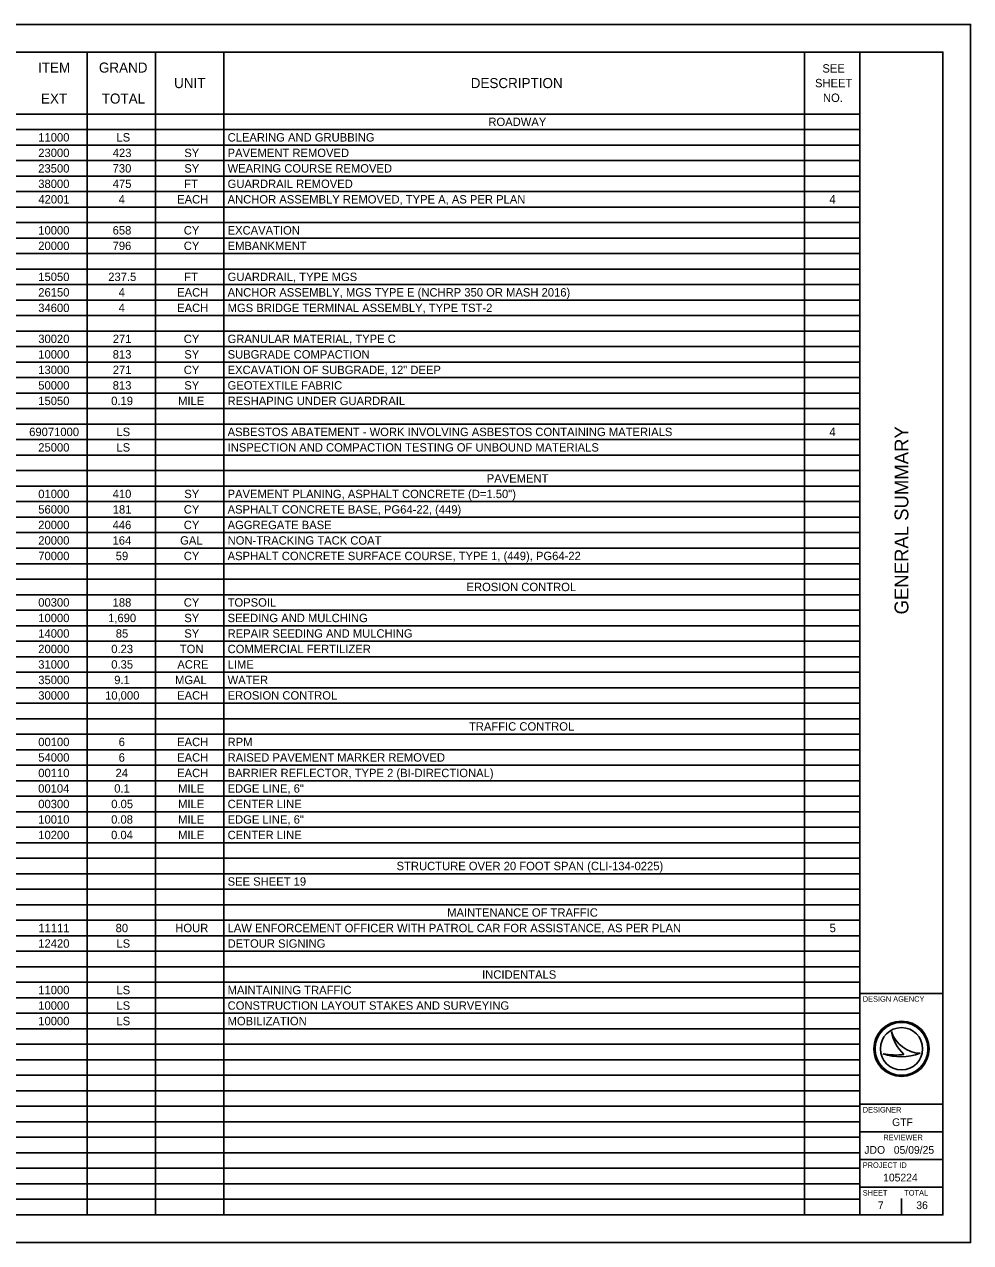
# Model space of a CAD drawing. Extents: x -98 to 34, y 0 to 58.
# Drawn here: x 16.9 to 34, y 0 to 22 of the extents above; entities that cross this region are included whole.
import ezdxf

# ---------------------------------------------------------------- set-up
doc = ezdxf.new("R2010")
doc.units = 0
for name, color, linetype in [('Default', 7, 'Continuous'), ('SH_Border', 7, 'Continuous'), ('SH_Cut_Line', 7, 'Continuous'), ('SH_Data', 7, 'Continuous')]:
    doc.layers.add(name, color=color, linetype=linetype)

msp = doc.modelspace()

# ---------------------------------------------------------------- linework, layer by layer
at = {"layer": 'Default'}
for p, q in [((1.5, 21.5), (32, 21.5)), ((18.035, 21.5), (18.035, 0.502)), ((19.27, 21.5), (19.27, 0.502)), ((20.505, 21.5), (20.505, 0.502)), ((30.995, 21.5), (30.995, 0.502)), ((32, 21.5), (32, 0.502)), ((1.5, 20.38), (32, 20.38)), ((1.5, 20.1), (32, 20.1)), ((1.5, 19.82), (32, 19.82)), ((1.5, 19.54), (32, 19.54)), ((1.5, 19.26), (32, 19.26)), ((1.5, 18.98), (32, 18.98)), ((1.5, 18.7), (32, 18.7)), ((1.5, 18.42), (32, 18.42)), ((1.5, 18.14), (32, 18.14)), ((1.5, 17.86), (32, 17.86)), ((1.5, 17.58), (32, 17.58)), ((1.5, 17.3), (32, 17.3)), ((1.5, 17.021), (32, 17.021)), ((1.5, 16.741), (32, 16.741)), ((1.5, 16.461), (32, 16.461)), ((1.5, 16.181), (32, 16.181)), ((1.5, 15.901), (32, 15.901)), ((1.5, 15.621), (32, 15.621)), ((1.5, 15.341), (32, 15.341)), ((1.5, 15.061), (32, 15.061)), ((1.5, 14.781), (32, 14.781)), ((1.5, 14.501), (32, 14.501)), ((1.5, 14.221), (32, 14.221)), ((1.5, 13.941), (32, 13.941)), ((1.5, 13.661), (32, 13.661)), ((1.5, 13.381), (32, 13.381)), ((1.5, 13.101), (32, 13.101)), ((1.5, 12.821), (32, 12.821)), ((1.5, 12.541), (32, 12.541)), ((1.5, 12.261), (32, 12.261)), ((1.5, 11.981), (32, 11.981)), ((1.5, 11.701), (32, 11.701)), ((1.5, 11.421), (32, 11.421)), ((1.5, 11.141), (32, 11.141)), ((1.5, 10.861), (32, 10.861)), ((1.5, 10.581), (32, 10.581)), ((1.5, 10.301), (32, 10.301)), ((1.5, 10.021), (32, 10.021)), ((1.5, 9.741), (32, 9.741)), ((1.5, 9.461), (32, 9.461)), ((1.5, 9.181), (32, 9.181)), ((1.5, 8.901), (32, 8.901)), ((1.5, 8.621), (32, 8.621)), ((1.5, 8.342), (32, 8.342)), ((1.5, 8.062), (32, 8.062)), ((1.5, 7.782), (32, 7.782)), ((1.5, 7.502), (32, 7.502)), ((1.5, 7.222), (32, 7.222)), ((1.5, 6.942), (32, 6.942)), ((1.5, 6.662), (32, 6.662)), ((1.5, 6.382), (32, 6.382)), ((1.5, 6.102), (32, 6.102)), ((1.5, 5.822), (32, 5.822)), ((1.5, 5.542), (32, 5.542)), ((1.5, 5.262), (32, 5.262)), ((1.5, 4.982), (32, 4.982)), ((1.5, 4.702), (32, 4.702)), ((1.5, 4.422), (32, 4.422)), ((1.5, 4.142), (32, 4.142)), ((1.5, 3.862), (32, 3.862)), ((1.5, 3.582), (32, 3.582)), ((1.5, 3.302), (32, 3.302)), ((1.5, 3.022), (32, 3.022)), ((1.5, 2.742), (32, 2.742)), ((1.5, 2.462), (32, 2.462)), ((1.5, 2.182), (32, 2.182)), ((1.5, 1.902), (32, 1.902)), ((1.5, 1.622), (32, 1.622)), ((1.5, 1.342), (32, 1.342)), ((1.5, 1.062), (32, 1.062)), ((1.5, 0.782), (32, 0.782)), ((1.5, 0.502), (32, 0.502))]:
    msp.add_line(p, q, dxfattribs=at)
at = {"layer": 'SH_Border'}
for p, q in [((32, 0.5), (32, 21.5)), ((32, 4.5), (33.5, 4.5)), ((32, 2.5), (33.5, 2.5)), ((32, 2), (33.5, 2)), ((32, 1.5), (33.5, 1.5)), ((32, 1), (33.5, 1))]:
    msp.add_line(p, q, dxfattribs=at)
msp.add_lwpolyline([(1.5, 21.5), (33.5, 21.5), (33.5, 0.5), (1.5, 0.5)], close=True, dxfattribs=at)
at = {"layer": 'SH_Cut_Line'}
msp.add_lwpolyline([(0, 0), (34, 0), (34, 22), (0, 22)], close=True, dxfattribs=at)
at = {"layer": 'SH_Data'}
for p, q in [((32.567, 3.81), (32.567, 3.81)), ((32.417, 3.41), (32.417, 3.41)), ((32.75, 3.5), (32.75, 3.5)), ((33.087, 3.419), (33.087, 3.419)), ((32.375, 0.675), (32.375, 0.675)), ((32.75, 0.5), (32.75, 0.8))]:
    msp.add_line(p, q, dxfattribs=at)
for radius in [0.5, 0.477, 0.477, 0.382]:
    msp.add_circle((32.75, 3.5), radius, dxfattribs=at)
for centre, radius, start, end in [((33.116, 3.998), 0.58, 198.9257, 198.9319), ((33.347, 3.97), 0.796, 191.6379, 191.6421), ((33.116, 3.998), 0.58, 198.9319, 267.1657), ((33.347, 3.97), 0.796, 191.6421, 226.0947), ((32.739, 4.37), 1.013, 251.4576, 290.0832), ((32.648, 4.654), 1.266, 259.4964, 259.4995), ((32.739, 4.37), 1.013, 251.4527, 251.4576), ((32.648, 4.654), 1.266, 259.4995, 276.6672)]:
    msp.add_arc(centre, radius, start, end, dxfattribs=at)

# ---------------------------------------------------------------- texts
at = {"layer": 'Default'}
for s, height, p in [('ITEM', 0.1818, (17.145, 21.129)), ('GRAND', 0.1818, (18.245, 21.129)), ('SEE ', 0.1515, (31.32, 21.129)), ('UNIT', 0.1818, (19.604, 20.849)), ('DESCRIPTION', 0.18181, (24.965, 20.849)), ('SHEET ', 0.1515, (31.187, 20.864)), ('EXT', 0.1818, (17.199, 20.569)), ('TOTAL', 0.1818, (18.297, 20.569)), ('NO.', 0.1515, (31.331, 20.599)), ('ROADWAY', 0.1515, (25.284, 20.164)), ('11000', 0.1515, (17.149, 19.884)), ('LS', 0.1515, (18.562, 19.884)), ('CLEARING AND GRUBBING', 0.15151, (20.571, 19.884)), ('23000', 0.1515, (17.149, 19.604)), ('423', 0.1515, (18.495, 19.604)), ('SY', 0.1515, (19.788, 19.604)), ('PAVEMENT REMOVED', 0.15151, (20.571, 19.604)), ('23500', 0.1515, (17.149, 19.324)), ('730', 0.1515, (18.493, 19.324)), ('SY', 0.1515, (19.788, 19.324)), ('WEARING COURSE REMOVED', 0.15151, (20.571, 19.324)), ('38000', 0.1515, (17.149, 19.045)), ('475', 0.1515, (18.495, 19.045)), ('FT', 0.1515, (19.786, 19.045)), ('GUARDRAIL REMOVED', 0.15151, (20.571, 19.045)), ('42001', 0.1515, (17.151, 18.765)), ('4', 0.152, (18.601, 18.765)), ('EACH', 0.1515, (19.659, 18.765)), ('ANCHOR ASSEMBLY REMOVED, TYPE A, AS PER PLAN', 0.15151, (20.571, 18.765)), ('4', 0.152, (31.446, 18.765)), ('10000', 0.1515, (17.149, 18.205)), ('658', 0.1515, (18.493, 18.205)), ('CY', 0.1515, (19.779, 18.205)), ('EXCAVATION', 0.1515, (20.571, 18.205)), ('20000', 0.1515, (17.149, 17.925)), ('796', 0.1515, (18.493, 17.925)), ('CY', 0.1515, (19.779, 17.925)), ('EMBANKMENT', 0.1515, (20.571, 17.925)), ('15050', 0.1515, (17.149, 17.365)), ('237.5', 0.1515, (18.414, 17.365)), ('FT', 0.1515, (19.786, 17.365)), ('GUARDRAIL, TYPE MGS', 0.15151, (20.571, 17.365)), ('26150', 0.1515, (17.149, 17.085)), ('4', 0.152, (18.601, 17.085)), ('EACH', 0.1515, (19.659, 17.085)), ('ANCHOR ASSEMBLY, MGS TYPE E (NCHRP 350 OR MASH 2016)', 0.15151, (20.571, 17.085)), ('34600', 0.1515, (17.149, 16.805)), ('4', 0.152, (18.601, 16.805)), ('EACH', 0.1515, (19.659, 16.805)), ('MGS BRIDGE TERMINAL ASSEMBLY, TYPE TST-2', 0.15151, (20.571, 16.805)), ('30020', 0.1515, (17.149, 16.245)), ('271', 0.1515, (18.495, 16.245)), ('CY', 0.1515, (19.779, 16.245)), ('GRANULAR MATERIAL, TYPE C', 0.15151, (20.571, 16.245)), ('10000', 0.1515, (17.149, 15.965)), ('813', 0.1515, (18.495, 15.965)), ('SY', 0.1515, (19.788, 15.965)), ('SUBGRADE COMPACTION', 0.15151, (20.571, 15.965)), ('13000', 0.1515, (17.149, 15.685)), ('271', 0.1515, (18.495, 15.685)), ('CY', 0.1515, (19.779, 15.685)), ('EXCAVATION OF SUBGRADE, 12" DEEP', 0.15151, (20.571, 15.685)), ('50000', 0.1515, (17.149, 15.405)), ('813', 0.1515, (18.495, 15.405)), ('SY', 0.1515, (19.788, 15.405)), ('GEOTEXTILE FABRIC', 0.15151, (20.571, 15.405)), ('15050', 0.1515, (17.149, 15.125)), ('0.19', 0.1515, (18.467, 15.125)), ('MILE', 0.1515, (19.676, 15.125)), ('RESHAPING UNDER GUARDRAIL', 0.15151, (20.571, 15.125)), ('69071000', 0.1515, (16.985, 14.565)), ('LS', 0.1515, (18.562, 14.565)), ('ASBESTOS ABATEMENT - WORK INVOLVING ASBESTOS CONTAINING MATERIALS', 0.15151, (20.571, 14.565)), ('4', 0.152, (31.446, 14.565)), ('25000', 0.1515, (17.149, 14.285)), ('LS', 0.1515, (18.562, 14.285)), ('INSPECTION AND COMPACTION TESTING OF UNBOUND MATERIALS', 0.15151, (20.571, 14.285)), ('PAVEMENT', 0.1515, (25.255, 13.725)), ('01000', 0.1515, (17.149, 13.445)), ('410', 0.1515, (18.493, 13.445)), ('SY', 0.1515, (19.788, 13.445)), ('PAVEMENT PLANING, ASPHALT CONCRETE (D=1.50")', 0.15151, (20.571, 13.445)), ('56000', 0.1515, (17.149, 13.165)), ('181', 0.1515, (18.495, 13.165)), ('CY', 0.1515, (19.779, 13.165)), ('ASPHALT CONCRETE BASE, PG64-22, (449)', 0.15151, (20.571, 13.165)), ('20000', 0.1515, (17.149, 12.885)), ('446', 0.1515, (18.493, 12.885)), ('CY', 0.1515, (19.779, 12.885)), ('AGGREGATE BASE', 0.15151, (20.571, 12.885)), ('20000', 0.1515, (17.149, 12.605)), ('164', 0.1515, (18.492, 12.605)), ('GAL', 0.1515, (19.713, 12.605)), ('NON-TRACKING TACK COAT', 0.15151, (20.571, 12.605)), ('70000', 0.1515, (17.149, 12.325)), ('59', 0.1515, (18.549, 12.325)), ('CY', 0.1515, (19.779, 12.325)), ('ASPHALT CONCRETE SURFACE COURSE, TYPE 1, (449), PG64-22', 0.15151, (20.571, 12.325)), ('EROSION CONTROL', 0.15151, (24.889, 11.765)), ('00300', 0.1515, (17.149, 11.485)), ('188', 0.1515, (18.493, 11.485)), ('CY', 0.1515, (19.779, 11.485)), ('TOPSOIL', 0.1515, (20.571, 11.485)), ('10000', 0.1515, (17.149, 11.205)), ('1,690', 0.1515, (18.411, 11.205)), ('SY', 0.1515, (19.788, 11.205)), ('SEEDING AND MULCHING', 0.15151, (20.571, 11.205)), ('14000', 0.1515, (17.149, 10.925)), ('85', 0.1515, (18.55, 10.925)), ('SY', 0.1515, (19.788, 10.925)), ('REPAIR SEEDING AND MULCHING', 0.15151, (20.571, 10.925)), ('20000', 0.1515, (17.149, 10.645)), ('0.23', 0.1515, (18.468, 10.645)), ('TON', 0.1515, (19.707, 10.645)), ('COMMERCIAL FERTILIZER', 0.15151, (20.571, 10.645)), ('31000', 0.1515, (17.149, 10.366)), ('0.35', 0.1515, (18.468, 10.366)), ('ACRE', 0.1515, (19.663, 10.366)), ('LIME', 0.1515, (20.571, 10.366)), ('35000', 0.1515, (17.149, 10.086)), ('9.1', 0.1515, (18.522, 10.086)), ('MGAL', 0.1515, (19.621, 10.086)), ('WATER', 0.1515, (20.571, 10.086)), ('30000', 0.1515, (17.149, 9.806)), ('10,000', 0.1515, (18.357, 9.806)), ('EACH', 0.1515, (19.659, 9.806)), ('EROSION CONTROL', 0.15151, (20.571, 9.806)), ('TRAFFIC CONTROL', 0.15151, (24.933, 9.246)), ('00100', 0.1515, (17.149, 8.966)), ('6', 0.152, (18.602, 8.966)), ('EACH', 0.1515, (19.659, 8.966)), ('RPM', 0.1515, (20.571, 8.966)), ('54000', 0.1515, (17.149, 8.686)), ('6', 0.152, (18.602, 8.686)), ('EACH', 0.1515, (19.659, 8.686)), ('RAISED PAVEMENT MARKER REMOVED', 0.15151, (20.571, 8.686)), ('00110', 0.1515, (17.149, 8.406)), ('24', 0.1515, (18.546, 8.406)), ('EACH', 0.1515, (19.659, 8.406)), ('BARRIER REFLECTOR, TYPE 2 (BI-DIRECTIONAL)', 0.15151, (20.571, 8.406)), ('00104', 0.1515, (17.148, 8.126)), ('0.1', 0.1515, (18.522, 8.126)), ('MILE', 0.1515, (19.676, 8.126)), ('EDGE LINE, 6"', 0.15151, (20.571, 8.126)), ('00300', 0.1515, (17.149, 7.846)), ('0.05', 0.1515, (18.468, 7.846)), ('MILE', 0.1515, (19.676, 7.846)), ('CENTER LINE', 0.15151, (20.571, 7.846)), ('10010', 0.1515, (17.149, 7.566)), ('0.08', 0.1515, (18.466, 7.566)), ('MILE', 0.1515, (19.676, 7.566)), ('EDGE LINE, 6"', 0.15151, (20.571, 7.566)), ('10200', 0.1515, (17.149, 7.286)), ('0.04', 0.1515, (18.465, 7.286)), ('MILE', 0.1515, (19.676, 7.286)), ('CENTER LINE', 0.15151, (20.571, 7.286)), ('STRUCTURE OVER 20 FOOT SPAN (CLI-134-0225)', 0.15151, (23.625, 6.726)), ('SEE SHEET 19', 0.15151, (20.571, 6.446)), ('MAINTENANCE OF TRAFFIC', 0.15151, (24.539, 5.886)), ('11111', 0.1515, (17.151, 5.606)), ('80', 0.1515, (18.547, 5.606)), ('HOUR', 0.1515, (19.626, 5.606)), ('LAW ENFORCEMENT OFFICER WITH PATROL CAR FOR ASSISTANCE, AS PER PLAN', 0.15151, (20.571, 5.606)), ('5', 0.152, (31.45, 5.606)), ('12420', 0.1515, (17.149, 5.326)), ('LS', 0.1515, (18.562, 5.326)), ('DETOUR SIGNING', 0.15151, (20.571, 5.326)), ('INCIDENTALS', 0.15151, (25.171, 4.766)), ('11000', 0.1515, (17.149, 4.486)), ('LS', 0.1515, (18.562, 4.486)), ('MAINTAINING TRAFFIC', 0.15151, (20.571, 4.486)), ('10000', 0.1515, (17.149, 4.206)), ('LS', 0.1515, (18.562, 4.206)), ('CONSTRUCTION LAYOUT STAKES AND SURVEYING', 0.15151, (20.571, 4.206)), ('10000', 0.1515, (17.149, 3.926)), ('LS', 0.1515, (18.562, 3.926)), ('MOBILIZATION', 0.15151, (20.571, 3.926))]:
    msp.add_text(s, height=height, dxfattribs=at).set_placement(p)
at = {"layer": 'SH_Data'}
msp.add_text('GENERAL SUMMARY', height=0.25, rotation=90, dxfattribs=at).set_placement((32.875, 11.344))
for s, height, p in [('DESIGN AGENCY', 0.1, (32.05, 4.35)), ('DESIGNER', 0.1, (32.05, 2.35)), ('GTF', 0.14, (32.581, 2.105)), ('REVIEWER', 0.1, (32.422, 1.85)), ('JDO', 0.14, (32.079, 1.605)), ('05/09/25', 0.14, (32.611, 1.605)), ('PROJECT ID', 0.1, (32.05, 1.35)), ('105224', 0.14, (32.418, 1.105)), ('SHEET', 0.1, (32.05, 0.85)), ('TOTAL', 0.1, (32.8, 0.85)), ('7', 0.14, (32.324, 0.605)), ('36', 0.14, (33.018, 0.605))]:
    msp.add_text(s, height=height, dxfattribs=at).set_placement(p)

doc.saveas('drawing.dxf')
